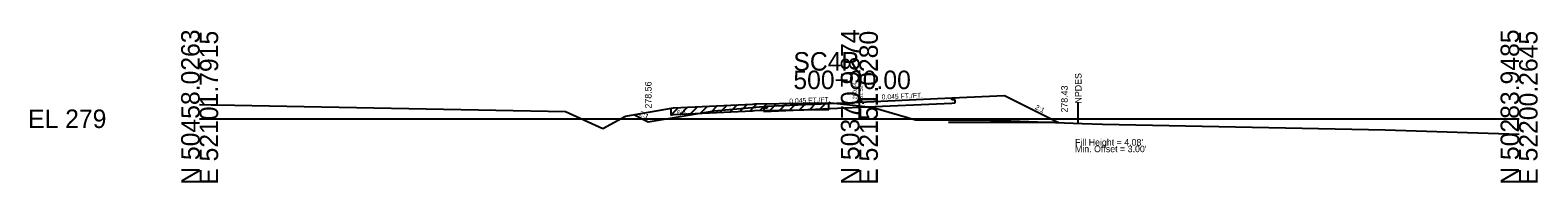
# Model space of a CAD drawing. Extents: x 7498 to 13027, y 90095 to 109625.
# Drawn here: x 8498.3 to 8726.8, y 90095.5 to 90118.6 of the extents above; entities that cross this region are included whole.
import ezdxf

# ---------------------------------------------------------------- set-up
doc = ezdxf.new("R2010")
doc.units = 0
for name, color, linetype in [('Level 10', 7, 'Continuous'), ('Level 11', 7, 'Continuous'), ('Level 12', 7, 'Continuous'), ('Level 32', 7, 'Continuous'), ('Level 33', 7, 'Continuous'), ('Level 50', 7, 'Continuous'), ('Level 55', 7, 'Continuous'), ('Level 59', 7, 'Continuous'), ('Level 6', 7, 'Continuous'), ('Level 60', 7, 'Continuous'), ('Level 61', 7, 'Continuous'), ('Level 63', 7, 'Continuous'), ('Level 7', 7, 'Continuous')]:
    doc.layers.add(name, color=color, linetype=linetype)

msp = doc.modelspace()

# ---------------------------------------------------------------- linework, layer by layer
at = {"layer": 'Level 11'}
for p, q in [((8637.99, 90108.01), (8637.99, 90108.31)), ((8638.49, 90108.03), (8637.99, 90108.01)), ((8637.99, 90107.53), (8638.49, 90107.55)), ((8638.49, 90107.55), (8638.49, 90108.03))]:
    msp.add_line(p, q, dxfattribs=at)
at = {"layer": 'Level 12'}
for p, q in [((8609.49, 90106.27), (8623.99, 90106.9)), ((8609.99, 90106.75), (8609.49, 90106.75)), ((8609.49, 90106.75), (8609.49, 90106.27)), ((8609.99, 90107.05), (8609.99, 90106.75)), ((8623.99, 90106.9), (8637.99, 90107.53))]:
    msp.add_line(p, q, dxfattribs=at)
at = {"layer": 'Level 55'}
for p, q in [((8657.16, 90104.58), (8657.16, 90107.58)), ((8654.16, 90104.58), (8637.5, 90104.58))]:
    msp.add_line(p, q, dxfattribs=at)
at = {"layer": 'Level 59'}
for p, q in [((8609.99, 90107.05), (8623.99, 90107.68)), ((8623.99, 90107.68), (8637.99, 90108.31))]:
    msp.add_line(p, q, dxfattribs=at)
at = {"layer": 'Level 6'}
for p, q in [((8601.99, 90106.38), (8609.99, 90107.05)), ((8637.99, 90108.31), (8645.99, 90108.67))]:
    msp.add_line(p, q, dxfattribs=at)
at = {"layer": 'Level 60'}
for p, q in [((8523.99, 90107.3), (8525.72, 90107.27)), ((8525.72, 90107.27), (8526.63, 90107.25)), ((8526.63, 90107.25), (8579.46, 90106.28)), ((8588.56, 90105.53), (8595.81, 90106.8)), ((8595.81, 90106.8), (8607.77, 90107.38)), ((8607.77, 90107.38), (8608.09, 90107.4)), ((8608.09, 90107.4), (8619.32, 90107.58)), ((8619.32, 90107.58), (8619.65, 90107.59)), ((8619.65, 90107.59), (8623.99, 90107.1)), ((8623.99, 90107.1), (8626.07, 90106.88)), ((8626.07, 90106.88), (8632.49, 90104.98)), ((8579.46, 90106.28), (8585.09, 90103.68)), ((8585.09, 90103.68), (8588.56, 90105.53)), ((8632.49, 90104.98), (8643.55, 90105.01)), ((8643.55, 90105.01), (8643.86, 90104.97)), ((8643.86, 90104.97), (8644.29, 90104.95)), ((8644.29, 90104.95), (8657.78, 90104.45)), ((8657.78, 90104.45), (8660.86, 90104.36)), ((8660.86, 90104.36), (8703.68, 90103.46)), ((8703.68, 90103.46), (8723.99, 90102.83))]:
    msp.add_line(p, q, dxfattribs=at)
at = {"layer": 'Level 61'}
for p, q in [((8596.51, 90106.84), (8595.41, 90105.73)), ((8595.41, 90106.73), (8595.41, 90105.73)), ((8597.96, 90106.91), (8596.91, 90105.86)), ((8599.46, 90106.98), (8598.41, 90105.93)), ((8600.96, 90107.05), (8599.91, 90106)), ((8602.46, 90107.12), (8601.41, 90106.07)), ((8603.96, 90107.2), (8602.91, 90106.15)), ((8605.47, 90107.27), (8604.41, 90106.22)), ((8606.97, 90107.34), (8605.92, 90106.29)), ((8608.46, 90107.4), (8607.42, 90106.36)), ((8608.09, 90106.4), (8619.32, 90106.58)), ((8609.94, 90107.43), (8608.92, 90106.41)), ((8611.44, 90107.45), (8610.42, 90106.43)), ((8612.94, 90107.48), (8611.92, 90106.46)), ((8614.44, 90107.5), (8613.42, 90106.48)), ((8615.94, 90107.53), (8614.92, 90106.51)), ((8617.44, 90107.55), (8616.42, 90106.53)), ((8618.94, 90107.58), (8617.93, 90106.56)), ((8619.32, 90106.58), (8619.35, 90106.58)), ((8619.35, 90106.58), (8619.35, 90107.58)), ((8595.41, 90105.73), (8595.81, 90105.8)), ((8595.81, 90105.8), (8607.77, 90106.38)), ((8607.77, 90106.38), (8608.09, 90106.4))]:
    msp.add_line(p, q, dxfattribs=at)
at = {"layer": 'Level 63'}
for p, q in [((8623.99, 90105.16), (8623.99, 90112.45)), ((8523.99, 90105.16), (8623.99, 90105.16)), ((8623.99, 90105.16), (8723.99, 90105.16))]:
    msp.add_line(p, q, dxfattribs=at)
at = {"layer": 'Level 7'}
for p, q in [((8645.99, 90108.67), (8654.16, 90104.58)), ((8589.89, 90105.77), (8591.99, 90104.71)), ((8591.99, 90104.71), (8601.99, 90106.38))]:
    msp.add_line(p, q, dxfattribs=at)

# ---------------------------------------------------------------- texts
at = {"layer": 'Level 10'}
msp.add_text('280.94', height=0.6, rotation=90, dxfattribs=at).set_placement((8623.59, 90108.1))
at = {"layer": 'Level 32'}
for s, rotation, p in [('0.045 FT./FT.', 2.5766, (8627.38, 90108.08)), ('6:1', 9.4623, (8596.43, 90105.71)), ('0.045 FT./FT.', 2.5766, (8613.38, 90107.45)), ('2:1', 333.435, (8650.55, 90106.67)), ('2:1', 333.435, (8590.55, 90105.72))]:
    msp.add_text(s, height=0.75, rotation=rotation, dxfattribs=at).set_placement(p)
at = {"layer": 'Level 33'}
for s, p in [('278.56', (8592.49, 90106.71)), ('278.43', (8655.57, 90106.1))]:
    msp.add_text(s, height=1, rotation=90, dxfattribs=at).set_placement(p)
at = {"layer": 'Level 50'}
msp.add_text(' NPDES', height=1, rotation=90, dxfattribs=at).set_placement((8657.67, 90107.1))
for s, p in [("Fill Height = 4.08' ", (8656.67, 90101.1)), ("Min. Offset = 3.00' ", (8656.67, 90100.1))]:
    msp.add_text(s, height=1, dxfattribs=at).set_placement(p)
at = {"layer": 'Level 59'}
msp.add_text(' 281.52', height=0.6, rotation=90, dxfattribs=at).set_placement((8624.51, 90107.48))
at = {"layer": 'Level 63'}
for s, p in [('N 50458.0263', (8523.99, 90095.16)), ('E 52101.7915', (8526.79, 90095.16)), ('N 50370.9874', (8623.99, 90095.16)), ('E 52151.0280', (8626.79, 90095.16)), ('N 50283.9485', (8723.99, 90095.16)), ('E 52200.2645', (8726.79, 90095.16))]:
    msp.add_text(s, height=2.8, rotation=90, dxfattribs=at).set_placement(p)
for s, p in [('SC4R', (8613.99, 90112.45)), ('500+00.00', (8613.99, 90109.65)), ('EL 279', (8497.99, 90103.76))]:
    msp.add_text(s, height=2.8, dxfattribs=at).set_placement(p)

doc.saveas('drawing.dxf')
